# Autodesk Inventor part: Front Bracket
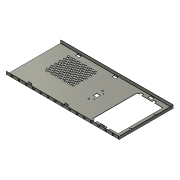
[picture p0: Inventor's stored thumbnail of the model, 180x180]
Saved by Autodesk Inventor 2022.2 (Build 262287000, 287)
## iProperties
Created: 2007-02
Part Number: Front Bracket
Material: アルミニウム 6061
Document SubType Name: Sheet Metal
Designer: Autodesk, Inc.
Mass: 151.269 g
Surface Area: 1172.88 cm^2
Volume: 56.0257 cm^3
Density: 2.7 g/cm^3
Flat Pattern Width: 19.4953 cm
Flat Pattern Length: 37.6477 cm
Flat Pattern Area: 733.953 cm^2
Sheet Metal Rule: 1 mm
Sheet Metal Width: 194.953 mm
Sheet Metal Length: 376.477 mm
Sheet Metal Area: 73395.269 mm^2
Appearance: Silicon Nitride - Polished
Author: Autodesk, Inc.
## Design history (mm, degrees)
node "Face1"
  sketch "Sketch1"
    geometry: L1 (-184, 89)-(184, 89); L2 (184, 89)-(184, -89); L3 (184, -89)-(-184, -89); L4 (-184, -89)-(-184, 89); L5 (-184, 89)-(184, -89); 2 further points
    constraints: 10 end point, 2 parallel, 1 coincident, 1 horizontal, 1 midpoint, 1 perpendicular
    dimensions: "d0" = 368 distance of L2.end L3.end; "d1" = 178 distance of L3.end L1.start
node "Flange1"
sketch "Sketch3" dims "d19" = 10, "d26" = 10
  geometry: L1 (0, 0)-(0, 8.5) reference; L2 (0, 8.5)-(366.293, 8.5) reference; 29 further points
  constraints: 2 horizontal, 28 other
  dimensions: "d12" = 18 distance from line of point (18, 4.5) L1; "d13" = 4 distance from line of L2 point (18, 4.5); "d16" = 330 distance of point (18, 4.5) point (348, 4.5); "d23" = 23.571 distance of point (18, 4.5) point (41.571, 4.5)
feature "iFeature5:1" sketch "Sketch3" dims "d28" = 1, "d29" = 2.5 (= 0.5 x d30), "d30" = 5, "d31" = 6, "d32" = 1, "d33" = 0.5, "d34" = 3 (= 0.5 x d31), "d35" = 1 (= d32)
sketch "Sketch4"
  geometry: L1 (-138, -73)-(-138, -79); L2 (-129, -73)-(-138, -73); L3 (-129, -79)-(-129, -73); L4 (-138, -79)-(-129, -79); L5 (-123, -73)-(-165, -73); L6 (-129, 73)-(-138, 73); L7 (-123, 73)-(-123, -73); L8 (-165, -73)-(-165, 73); L9 (-165, 73)-(-123, 73); L10 (-138, 79)-(-129, 79); L11 (-138, 73)-(-138, 79); L12 (-129, 79)-(-129, 73); L13 (-184, -87.293)-(-184, 87.293) reference; L14 (184, -89)-(-182.293, -89) reference; 3 further points
  constraints: 24 end point, 6 parallel, 3 collinear, 3 horizontal, 3 perpendicular, 2 point on line
  dimensions: "d46" = 146 distance of L5.end L8.end; "d48" = 9 distance of L10.start L10.end; "d49" = 27 distance between parallel lines of L8 L11; "d50" = 42 distance between parallel lines of L7 L8; "d51" = 19 distance between parallel lines of L13 L8; "d52" = 16 distance between parallel lines of L14 L5
cut "Cut1" sketch "Sketch4" dims "d53" = 1 (= Thickness), "d54" = 0
pattern_linear "Rectangular Pattern1" dims "d57" = 42
sketch "Sketch5"
  geometry: L1 (-123.5, 83.5)-(-111.5, 83.5); L2 (-111.5, 83.5)-(-111.5, 77.5); L3 (-111.5, 77.5)-(-123.5, 77.5); L4 (-123.5, 77.5)-(-123.5, 83.5); L5 (-184, -87.293)-(-184, 87.293) reference; L6 (-182.293, 89)-(184, 89) reference; L7 (-6, 83.5)-(6, 83.5); L8 (6, 83.5)-(6, 77.5); L9 (6, 77.5)-(-6, 77.5); L10 (-6, 77.5)-(-6, 83.5); L11 (113, 83.5)-(125, 83.5); L12 (125, 83.5)-(125, 77.5); L13 (125, 77.5)-(113, 77.5); L14 (113, 77.5)-(113, 83.5); L15 (257.6, 0)-(-257.6, 0) reference; L16 (-111.5, -83.5)-(-111.5, -77.5); L17 (-123.5, -83.5)-(-111.5, -83.5); L18 (-111.5, -77.5)-(-123.5, -77.5); L19 (-123.5, -77.5)-(-123.5, -83.5); L20 (-6, -77.5)-(-6, -83.5); L21 (-6, -83.5)-(6, -83.5); L22 (6, -77.5)-(-6, -77.5); L23 (6, -83.5)-(6, -77.5); L24 (113, -77.5)-(113, -83.5); L25 (125, -83.5)-(125, -77.5); L26 (113, -83.5)-(125, -83.5); L27 (125, -77.5)-(113, -77.5); 7 further points
  constraints: 48 end point, 14 symmetric about line, 6 parallel, 4 point on line, 3 horizontal, 3 perpendicular, 2 collinear, 2 midpoint
  dimensions: "d58" = 12 distance of L2.end L3.end; "d59" = 6 distance of L3.end L1.start; "d60" = 60.5 distance between parallel lines of L5 L4; "d61" = 5.5 distance between parallel lines of L6 L1; "d62" = 12 distance of L8.end L9.end; "d63" = 12 distance of L12.end L13.end; "d64" = 117.5 distance between parallel lines of L10 L4; "d65" = 119 distance between parallel lines of L14 L10
cut "Cut2" sketch "Sketch5" dims "d66" = 1 (= Thickness), "d67" = 0
node "Flange2"
sketch "Sketch7"
  geometry: L1 (184, -87.5)-(184, 87.5) reference; L2 (-182.293, 89)-(184, 89) reference; L3 (130, 57.072)-(126, 64); L4 (126, 64)-(134, 64); L5 (134, 64)-(130, 57.072); 146 further points
  constraints: 6 end point, 2 coincident, 2 horizontal, 1 vertical, 149 other
  dimensions: "d77" = 50 distance from line of point (134, 64) L1; "d78" = 25 distance from line of L2 point (134, 64); "d79" = 8 distance of L3.end L4.end; "d82" = 8 distance of point (134, 64) point (126, 64); "d85" = 13.856 distance of point (134, 64) point (134, 50.144)
feature "iFeature6:1" sketch "Sketch7" dims "d88" = 6
sketch "Sketch8"
  geometry: L1 (-172, 40)-(-172, -40); L2 (-184, -87.293)-(-184, 87.293) reference; L3 (257.6, 0)-(-257.6, 0) reference; 3 further points
  constraints: 2 end point, 1 midpoint, 1 point on line, 1 vertical
  dimensions: "d90" = 80 distance of L1.start L1.end; "d91" = 12 distance from line of L2 L1.start
feature "iFeature6:2" sketch "Sketch8" dims "d92" = 6
sketch "Sketch9"
  geometry: L1 (-29, 15)-(-29, -15); L2 (-184, -87.293)-(-184, 87.293) reference; L3 (257.6, 0)-(-257.6, 0) reference; 3 further points
  constraints: 2 end point, 1 midpoint, 1 point on line, 1 vertical
  dimensions: "d94" = 30 distance of L1.start L1.end; "d95" = 155 distance from line of L2 L1.start
feature "iFeature9:1" sketch "Sketch9" dims "d96" = 2.5
sketch "Sketch10"
  geometry: L1 (-18.5, -22.5)-(-18.5, 22.5); L2 (-184, -87.293)-(-184, 87.293) reference; L3 (257.6, 0)-(-257.6, 0) reference; 3 further points
  constraints: 2 end point, 1 midpoint, 1 point on line, 1 vertical
  dimensions: "d98" = 45 distance of L1.start L1.end; "d99" = 165.5 distance from line of L2 L1.end
feature "iFeature8:1" sketch "Sketch10" dims "d100" = 5
sketch "Sketch11"
  geometry: L1 (257.6, 0)-(-257.6, 0) reference; L2 (-184, -87.293)-(-184, 87.293) reference; 3 further points
  constraints: 1 point on line
  dimensions: "d102" = 162 distance from line of L2 point (-22, 0)
feature "iFeature7:1" sketch "Sketch11" dims "d103" = 12 (= d104), "d104" = 12
body "Solid1"
face "Plate1" dims "d108" = 1 (= Thickness)
sketch "Sketch2"
  geometry: L1 (0, 10)-(-368, 10); L2 (-368, 10)-(-368, 0); 1 other entity
  constraints: 4 end point, 4 other
face "Plate2" dims "d3" = 1 (= BendReliefWidth), "d4" = 0.5 (= BendReliefDepth), "d5" = 2 (= MinimumRemnant), "d6" = 0.5 (= BendRadius), "d7" = 10, "d8" = 90 deg, "d9" = 0.5 (= BendRadius), "d10" = 4 (= CornerReliefSize), "d11" = 1 (= Thickness), "d106" = 1 (= JacobiRadiusSize), "d108" = 1 (= Thickness), "SeamGap" = 0.01
bend "Bend1" dims "d3" = 1 (= BendReliefWidth), "d4" = 0.5 (= BendReliefDepth), "d5" = 2 (= MinimumRemnant), "d6" = 0.5 (= BendRadius), "d7" = 10, "d8" = 90 deg, "d9" = 0.5 (= BendRadius), "d108" = 1 (= Thickness), "SeamGap" = 0.01
feature "Corner1" dims "d7" = 10, "d8" = 90 deg, "d10" = 4 (= CornerReliefSize), "d11" = 1 (= Thickness), "d106" = 1 (= JacobiRadiusSize)
sketch "Sketch6"
  geometry: L1 (-11.99, 0)-(-0.01, 0); L2 (-0.01, 0)-(-0.01, 5); L3 (-0.01, 5)-(-11.99, 5); L4 (-11.99, 5)-(-11.99, 0)
  constraints: 8 end point
face "Plate3" dims "d68" = 1 (= BendReliefWidth), "d69" = 0.5 (= BendReliefDepth), "d70" = 2 (= MinimumRemnant), "d71" = 0.5 (= BendRadius), "d72" = 5, "d73" = 90 deg, "d74" = 0.5 (= BendRadius), "d75" = 4 (= CornerReliefSize), "d76" = 1 (= Thickness), "d107" = 1 (= JacobiRadiusSize), "d108" = 1 (= Thickness), "SeamGap" = 0.01
bend "Bend2" dims "d68" = 1 (= BendReliefWidth), "d69" = 0.5 (= BendReliefDepth), "d70" = 2 (= MinimumRemnant), "d71" = 0.5 (= BendRadius), "d72" = 5, "d73" = 90 deg, "d74" = 0.5 (= BendRadius), "d108" = 1 (= Thickness), "SeamGap" = 0.01
feature "Corner2" dims "d72" = 5, "d73" = 90 deg, "d75" = 4 (= CornerReliefSize), "d76" = 1 (= Thickness), "d107" = 1 (= JacobiRadiusSize)
feature "Definition1" dims "d0" = 1 (derived)
other parameters: "Thickness" = 1, "BendRadius" = 0.5 (derived), "BendReliefWidth" = 1 (= Thickness), "BendReliefDepth" = 0.5 (= 0.5 x Thickness), "CornerReliefSize" = 4 (= 4 x Thickness), "MinimumRemnant" = 2 (= 2 x Thickness), "TransitionRadius" = 0.5 (= BendRadius), "JacobiRadiusSize" = 1 (= Thickness), "d2" = 0.5 (= BendRadius), "d37" = -90 deg, "d89" = 0, "d93" = 0, "d97" = 0, "d101" = 0, "d105" = 0, "GapSize" = 1 (= Thickness), "BendRadius" = 0.5, "BendReliefDepth" = 0.5, "BendReliefWidth" = 1, "CornerReliefSize" = 4, "JacobiRadiusSize" = 1, "MinimumRemnant" = 2, "Thickness" = 1, "TransitionRadius" = 0.5, "GapSize" = 1
